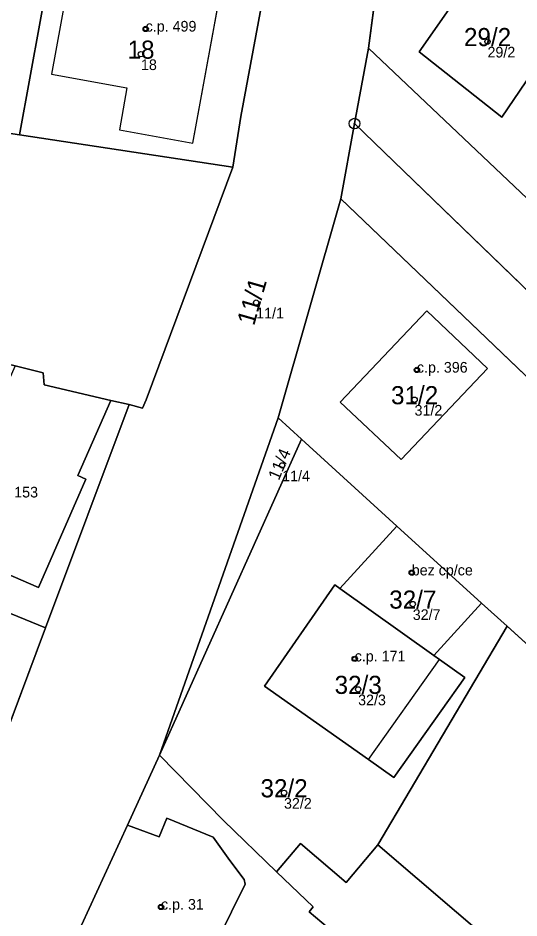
# Model space of a CAD drawing. Extents: x -603967 to -594699, y -1179315 to -1165625.
# Drawn here: x -597420.7 to -597373.7, y -1172555.6 to -1172471.2 of the extents above; entities that cross this region are included whole.
import ezdxf

# ---------------------------------------------------------------- set-up
doc = ezdxf.new("R2010")
doc.units = 0
for name, color, linetype in [('Definiční body', 7, 'Continuous'), ('Hranice parcel', 7, 'Continuous'), ('Parcelní čísla', 7, 'Continuous'), ('Polygon budovy', 7, 'Continuous'), ('Polygon parcely', 7, 'Continuous'), ('Vnitřní kresba', 7, 'Continuous'), ('Značky bodu BP', 7, 'Continuous'), ('Značky budov', 7, 'Continuous')]:
    doc.layers.add(name, color=color, linetype=linetype)

msp = doc.modelspace()

# ---------------------------------------------------------------- linework, layer by layer
at = {"layer": 'Definiční body'}
for centre in [(-597408.69, -1172472.22994), (-597376.64, -1172473.41994), (-597409.13, -1172474.59994), (-597398.33, -1172497.89994), (-597383.26, -1172504.21994), (-597383.48, -1172507.00994), (-597395.89, -1172513.16994), (-597383.74, -1172523.23994), (-597383.65, -1172526.17994), (-597389.09, -1172531.30994), (-597388.77, -1172534.17994), (-597395.72, -1172543.87994), (-597407.25, -1172554.58994)]:
    msp.add_circle(centre, 0.25, dxfattribs=at)
at = {"layer": 'Hranice parcel'}
for p, q in [((-597387.81, -1172474.04), (-597385.71, -1172458.2)), ((-597389.11, -1172481.11), (-597387.81, -1172474.04)), ((-597387.81, -1172474.04), (-597368.17, -1172492.64)), ((-597454.45, -1172476.98), (-597420.52, -1172482.15)), ((-597390.4, -1172488.17), (-597389.11, -1172481.11)), ((-597389.11, -1172481.11), (-597279.75, -1172586.8)), ((-597420.52, -1172482.15), (-597400.52, -1172485.2)), ((-597396.27, -1172508.71), (-597390.4, -1172488.17)), ((-597288.83, -1172585.38), (-597390.4, -1172488.17)), ((-597410.25, -1172507.47), (-597418.08, -1172528.4)), ((-597407.39, -1172540.35), (-597396.27, -1172508.71)), ((-597396.27, -1172508.71), (-597394.07, -1172510.72)), ((-597394.07, -1172510.72), (-597407.39, -1172540.35)), ((-597385.13, -1172518.86), (-597394.07, -1172510.72)), ((-597390.48, -1172524.71), (-597385.13, -1172518.86)), ((-597385.13, -1172518.86), (-597377.19, -1172526.09)), ((-597381.67, -1172530.99), (-597390.48, -1172524.71)), ((-597418.08, -1172528.4), (-597423.99, -1172526.01)), ((-597377.19, -1172526.09), (-597381.67, -1172530.99)), ((-597374.79, -1172528.26), (-597377.19, -1172526.09)), ((-597418.08, -1172528.4), (-597424.82, -1172546.4)), ((-597374.79, -1172528.26), (-597386.91, -1172548.77)), ((-597365.39, -1172536.83), (-597374.79, -1172528.26))]:
    msp.add_line(p, q, dxfattribs=at)
for points in [[(-597415.21, -1172463.61), (-597415.7, -1172466.4), (-597415.72, -1172466.54), (-597417.6, -1172466.2), (-597420.52, -1172482.15)], [(-597368.71, -1172470.95), (-597368.79, -1172471.06), (-597369.67, -1172472.21), (-597375.31, -1172480.52), (-597383.04, -1172474.38), (-597378.72, -1172468.18), (-597379.51, -1172467.7), (-597377.65, -1172464.65)], [(-597397.2, -1172466.61), (-597399.77, -1172480.46), (-597400.52, -1172485.2)], [(-597400.52, -1172485.2), (-597408.65, -1172507.01), (-597408.98, -1172507.8), (-597410.25, -1172507.47)], [(-597376.63, -1172504.07), (-597384.74, -1172512.63), (-597390.44, -1172507.23), (-597382.32, -1172498.68), (-597376.63, -1172504.07)], [(-597427.5, -1172502.26), (-597420.93, -1172503.84), (-597418.29, -1172504.48), (-597418.2, -1172505.62), (-597411.97, -1172507.07), (-597410.25, -1172507.47)], [(-597381.67, -1172530.99), (-597381.13, -1172531.38), (-597378.75, -1172533.08), (-597385.43, -1172542.46), (-597387.8, -1172540.77), (-597397.56, -1172533.87), (-597390.94, -1172524.38), (-597390.48, -1172524.71)], [(-597386.91, -1172548.77), (-597372.16, -1172561.4), (-597360.77, -1172566.23), (-597352.7, -1172567.75), (-597347.73, -1172562.26), (-597369.95, -1172541.78), (-597365.39, -1172536.83)], [(-597416.86, -1172561), (-597410.39, -1172546.93), (-597407.39, -1172540.35)], [(-597407.39, -1172540.35), (-597401.38, -1172546.47), (-597396.41, -1172551.29)], [(-597396.41, -1172551.29), (-597394.17, -1172548.63), (-597389.88, -1172552.3), (-597386.91, -1172548.77)], [(-597396.41, -1172551.29), (-597393, -1172554.59), (-597393.35, -1172555.05), (-597390.39, -1172557.56)]]:
    msp.add_lwpolyline(points, dxfattribs=at)
at = {"layer": 'Polygon budovy'}
for points in [[(-597378.72, -1172468.18), (-597383.04, -1172474.38), (-597375.31, -1172480.52), (-597369.67, -1172472.21), (-597368.79, -1172471.06), (-597368.71, -1172470.95), (-597376.72, -1172465.31), (-597377.65, -1172464.65), (-597379.51, -1172467.7)], [(-597415.72, -1172466.54), (-597417.53, -1172476.46), (-597410.45, -1172477.75), (-597411.14, -1172481.69), (-597404.26, -1172482.95), (-597401.71, -1172468.93), (-597415.7, -1172466.4)], [(-597390.44, -1172507.23), (-597384.74, -1172512.63), (-597376.63, -1172504.07), (-597382.32, -1172498.68)], [(-597423.8, -1172510.28), (-597429.76, -1172523.62), (-597423.99, -1172526.01), (-597422.59, -1172522.98), (-597418.73, -1172524.62), (-597414.3, -1172514.46), (-597415.05, -1172514.13), (-597411.97, -1172507.07), (-597418.2, -1172505.62), (-597418.29, -1172504.48), (-597420.93, -1172503.84)], [(-597385.13, -1172518.86), (-597390.48, -1172524.71), (-597381.67, -1172530.99), (-597377.19, -1172526.09)], [(-597390.94, -1172524.38), (-597397.56, -1172533.87), (-597387.8, -1172540.77), (-597381.13, -1172531.38), (-597381.67, -1172530.99), (-597390.48, -1172524.71)], [(-597394.17, -1172548.63), (-597396.41, -1172551.29), (-597393, -1172554.59), (-597393.35, -1172555.05), (-597390.39, -1172557.56), (-597387.18, -1172559.63), (-597383.87, -1172562.08), (-597376.76, -1172567.34), (-597368.87, -1172572.38), (-597335.41, -1172578.2), (-597328.59, -1172570.86), (-597328.33, -1172570.58), (-597365.39, -1172536.83), (-597369.95, -1172541.78), (-597347.73, -1172562.26), (-597352.7, -1172567.75), (-597360.77, -1172566.23), (-597372.16, -1172561.4), (-597386.91, -1172548.77), (-597389.88, -1172552.3)]]:
    msp.add_lwpolyline(points, close=True, dxfattribs=at)
msp.add_lwpolyline([(-597404.52, -1172562.88), (-597399.35, -1172552.46), (-597399.46, -1172552.01), (-597400.79, -1172550.23), (-597402.36, -1172548.03), (-597406.7, -1172546.25), (-597407.42, -1172548.02), (-597410.39, -1172546.93), (-597416.86, -1172561)], dxfattribs=at)
at = {"layer": 'Polygon parcely'}
for points in [[(-597422.26, -1172576.76), (-597418.4, -1172568.61), (-597419.94, -1172567.92), (-597416.86, -1172561), (-597410.39, -1172546.93), (-597407.39, -1172540.35), (-597396.27, -1172508.71), (-597390.4, -1172488.17), (-597389.11, -1172481.11), (-597387.81, -1172474.04), (-597385.71, -1172458.2)], [(-597397.2, -1172466.61), (-597399.77, -1172480.46), (-597400.52, -1172485.2), (-597408.65, -1172507.01), (-597408.98, -1172507.8), (-597410.25, -1172507.47), (-597418.08, -1172528.4), (-597424.82, -1172546.4)]]:
    msp.add_lwpolyline(points, dxfattribs=at)
for points in [[(-597360.97, -1172479.73), (-597361.85, -1172478.73), (-597368.71, -1172470.95), (-597368.79, -1172471.06), (-597369.67, -1172472.21), (-597375.31, -1172480.52), (-597383.04, -1172474.38), (-597378.72, -1172468.18), (-597379.51, -1172467.7), (-597377.65, -1172464.65), (-597385.71, -1172458.2), (-597387.81, -1172474.04), (-597368.17, -1172492.64), (-597361.68, -1172483.01), (-597363, -1172481.51)], [(-597447.95, -1172474.85), (-597452.13, -1172474.23), (-597450.4, -1172463.11), (-597449.89, -1172460.06), (-597452.36, -1172459.87), (-597454.45, -1172476.98), (-597420.52, -1172482.15), (-597417.6, -1172466.2), (-597415.72, -1172466.54), (-597415.7, -1172466.4), (-597415.21, -1172463.61), (-597409.88, -1172464.25), (-597409.49, -1172463.2), (-597445.68, -1172460.39), (-597446.19, -1172463.78), (-597442.27, -1172464.4), (-597444.01, -1172475.4)], [(-597415.7, -1172466.4), (-597415.72, -1172466.54), (-597417.6, -1172466.2), (-597420.52, -1172482.15), (-597400.52, -1172485.2), (-597399.77, -1172480.46), (-597397.2, -1172466.61), (-597406.74, -1172464.82), (-597409.88, -1172464.25), (-597415.21, -1172463.61)], [(-597368.71, -1172470.95), (-597376.72, -1172465.31), (-597377.65, -1172464.65), (-597379.51, -1172467.7), (-597378.72, -1172468.18), (-597383.04, -1172474.38), (-597375.31, -1172480.52), (-597369.67, -1172472.21), (-597368.79, -1172471.06)], [(-597447.46, -1172497.41), (-597427.5, -1172502.26), (-597420.93, -1172503.84), (-597418.29, -1172504.48), (-597418.2, -1172505.62), (-597411.97, -1172507.07), (-597410.25, -1172507.47), (-597408.98, -1172507.8), (-597408.65, -1172507.01), (-597400.52, -1172485.2), (-597420.52, -1172482.15), (-597454.45, -1172476.98), (-597470.37, -1172474.54), (-597472.64, -1172490.37), (-597472.89, -1172491.36), (-597466.39, -1172492.92), (-597462.64, -1172493.8)], [(-597267.25, -1172588.25), (-597283.55, -1172572.81), (-597298.1, -1172559.02), (-597312.66, -1172545.23), (-597327.21, -1172531.44), (-597368.17, -1172492.64), (-597387.81, -1172474.04), (-597389.11, -1172481.11), (-597279.75, -1172586.8)], [(-597389.11, -1172481.11), (-597390.4, -1172488.17), (-597288.83, -1172585.38), (-597280, -1172586.77), (-597279.75, -1172586.8)], [(-597394.07, -1172510.72), (-597385.13, -1172518.86), (-597377.19, -1172526.09), (-597374.79, -1172528.26), (-597365.39, -1172536.83), (-597328.33, -1172570.58), (-597316.19, -1172581.54), (-597309.69, -1172582.55), (-597294.77, -1172584.44), (-597288.83, -1172585.38), (-597390.4, -1172488.17), (-597396.27, -1172508.71)], [(-597376.63, -1172504.07), (-597384.74, -1172512.63), (-597390.44, -1172507.23), (-597382.32, -1172498.68)], [(-597376.63, -1172504.07), (-597382.32, -1172498.68), (-597390.44, -1172507.23), (-597384.74, -1172512.63)], [(-597427.5, -1172502.26), (-597434.01, -1172521.36), (-597434.16, -1172521.81), (-597429.76, -1172523.62), (-597423.99, -1172526.01), (-597418.08, -1172528.4), (-597410.25, -1172507.47), (-597411.97, -1172507.07), (-597418.2, -1172505.62), (-597418.29, -1172504.48), (-597420.93, -1172503.84)], [(-597407.39, -1172540.35), (-597394.07, -1172510.72), (-597396.27, -1172508.71)], [(-597374.79, -1172528.26), (-597377.19, -1172526.09), (-597381.67, -1172530.99), (-597381.13, -1172531.38), (-597378.75, -1172533.08), (-597385.43, -1172542.46), (-597387.8, -1172540.77), (-597397.56, -1172533.87), (-597390.94, -1172524.38), (-597390.48, -1172524.71), (-597385.13, -1172518.86), (-597394.07, -1172510.72), (-597407.39, -1172540.35), (-597401.38, -1172546.47), (-597396.41, -1172551.29), (-597394.17, -1172548.63), (-597389.88, -1172552.3), (-597386.91, -1172548.77)], [(-597454.74, -1172515.13), (-597459.42, -1172526.51), (-597436.37, -1172539.5), (-597431.39, -1172542.18), (-597424.82, -1172546.4), (-597418.08, -1172528.4), (-597423.99, -1172526.01), (-597429.76, -1172523.62), (-597434.16, -1172521.81), (-597434.01, -1172521.36), (-597436.52, -1172520.28), (-597440.33, -1172518.64), (-597441.21, -1172520.81), (-597444.84, -1172519.15)], [(-597381.67, -1172530.99), (-597377.19, -1172526.09), (-597385.13, -1172518.86), (-597390.48, -1172524.71)], [(-597390.48, -1172524.71), (-597390.94, -1172524.38), (-597397.56, -1172533.87), (-597387.8, -1172540.77), (-597385.43, -1172542.46), (-597378.75, -1172533.08), (-597381.13, -1172531.38), (-597381.67, -1172530.99)], [(-597347.73, -1172562.26), (-597369.95, -1172541.78), (-597365.39, -1172536.83), (-597374.79, -1172528.26), (-597386.91, -1172548.77), (-597372.16, -1172561.4), (-597360.77, -1172566.23), (-597352.7, -1172567.75)], [(-597383.87, -1172562.08), (-597376.76, -1172567.34), (-597368.87, -1172572.38), (-597335.41, -1172578.2), (-597321.16, -1172580.72), (-597316.19, -1172581.54), (-597328.33, -1172570.58), (-597365.39, -1172536.83), (-597369.95, -1172541.78), (-597347.73, -1172562.26), (-597352.7, -1172567.75), (-597360.77, -1172566.23), (-597372.16, -1172561.4), (-597386.91, -1172548.77), (-597389.88, -1172552.3), (-597394.17, -1172548.63), (-597396.41, -1172551.29), (-597393, -1172554.59), (-597393.35, -1172555.05), (-597390.39, -1172557.56), (-597387.18, -1172559.63)], [(-597382.79, -1172576.06), (-597382.18, -1172574.51), (-597380.6, -1172570.41), (-597383.2, -1172569.39), (-597382.98, -1172568.79), (-597384.72, -1172568.15), (-597384.94, -1172568.74), (-597391.33, -1172566.21), (-597389.72, -1172563.66), (-597393.48, -1172561.03), (-597390.39, -1172557.56), (-597393.35, -1172555.05), (-597393, -1172554.59), (-597396.41, -1172551.29), (-597401.38, -1172546.47), (-597407.39, -1172540.35), (-597410.39, -1172546.93), (-597416.86, -1172561), (-597397.81, -1172569.4), (-597394.05, -1172571.04), (-597390.13, -1172572.75)]]:
    msp.add_lwpolyline(points, close=True, dxfattribs=at)
at = {"layer": 'Vnitřní kresba'}
for p, q in [((-597404.26, -1172482.95), (-597401.71, -1172468.93)), ((-597410.45, -1172477.75), (-597411.14, -1172481.69)), ((-597411.14, -1172481.69), (-597404.26, -1172482.95)), ((-597411.97, -1172507.07), (-597415.05, -1172514.13)), ((-597415.05, -1172514.13), (-597414.3, -1172514.46)), ((-597414.3, -1172514.46), (-597418.73, -1172524.62)), ((-597418.73, -1172524.62), (-597422.59, -1172522.98)), ((-597387.8, -1172540.77), (-597381.13, -1172531.38)), ((-597407.42, -1172548.02), (-597406.7, -1172546.25)), ((-597406.7, -1172546.25), (-597402.36, -1172548.03)), ((-597410.39, -1172546.93), (-597407.42, -1172548.02)), ((-597402.36, -1172548.03), (-597400.79, -1172550.23)), ((-597400.79, -1172550.23), (-597399.46, -1172552.01)), ((-597399.46, -1172552.01), (-597399.35, -1172552.46)), ((-597399.35, -1172552.46), (-597404.52, -1172562.88))]:
    msp.add_line(p, q, dxfattribs=at)
msp.add_lwpolyline([(-597415.72, -1172466.54), (-597417.53, -1172476.46), (-597410.45, -1172477.75)], dxfattribs=at)
at = {"layer": 'Značky bodu BP'}
for radius in [0.5, 0.0303]:
    msp.add_circle((-597389.11, -1172481.10988), radius, dxfattribs=at)
at = {"layer": 'Značky budov'}
for centre in [(-597408.6968, -1172472.22916), (-597383.2668, -1172504.21916), (-597383.7468, -1172523.23916), (-597389.0968, -1172531.30916), (-597407.2568, -1172554.58916)]:
    msp.add_circle(centre, 0.175, dxfattribs=at)

# ---------------------------------------------------------------- texts
at = {"layer": 'Definiční body'}
for s, p in [('c.p. 499', (-597408.69, -1172472.48)), ('29/2', (-597376.64, -1172474.909)), ('18', (-597409.13, -1172476.089)), ('11/1', (-597398.33, -1172499.389)), ('c.p. 396', (-597383.26, -1172504.47)), ('31/2', (-597383.48, -1172508.499)), ('11/4', (-597395.89, -1172514.659)), ('c.p. 153', (-597423.54, -1172516.18)), ('bez cp/ce', (-597383.74, -1172523.49)), ('32/7', (-597383.65, -1172527.669)), ('c.p. 171', (-597389.09, -1172531.56)), ('32/3', (-597388.77, -1172535.669)), ('32/2', (-597395.72, -1172545.369)), ('c.p. 31', (-597407.25, -1172554.84))]:
    msp.add_text(s, height=0.999996, dxfattribs=at).set_placement(p)
at = {"layer": 'Parcelní čísla'}
for s, p in [('29/2', (-597378.845, -1172473.845)), ('18', (-597410.39, -1172475.025)), ('31/2', (-597385.685, -1172507.435)), ('32/7', (-597385.855, -1172526.605)), ('32/3', (-597390.975, -1172534.605)), ('32/2', (-597397.925, -1172544.305))]:
    msp.add_text(s, height=1.699998, dxfattribs=at).set_placement(p)
for s, height, rotation, p in [('11/1', 1.699998, 74, (-597398.529, -1172500.137)), ('11/4', 1.14, 66.9999972, (-597396.205, -1172514.642))]:
    msp.add_text(s, height=height, rotation=rotation, dxfattribs=at).set_placement(p)

doc.saveas('drawing.dxf')
